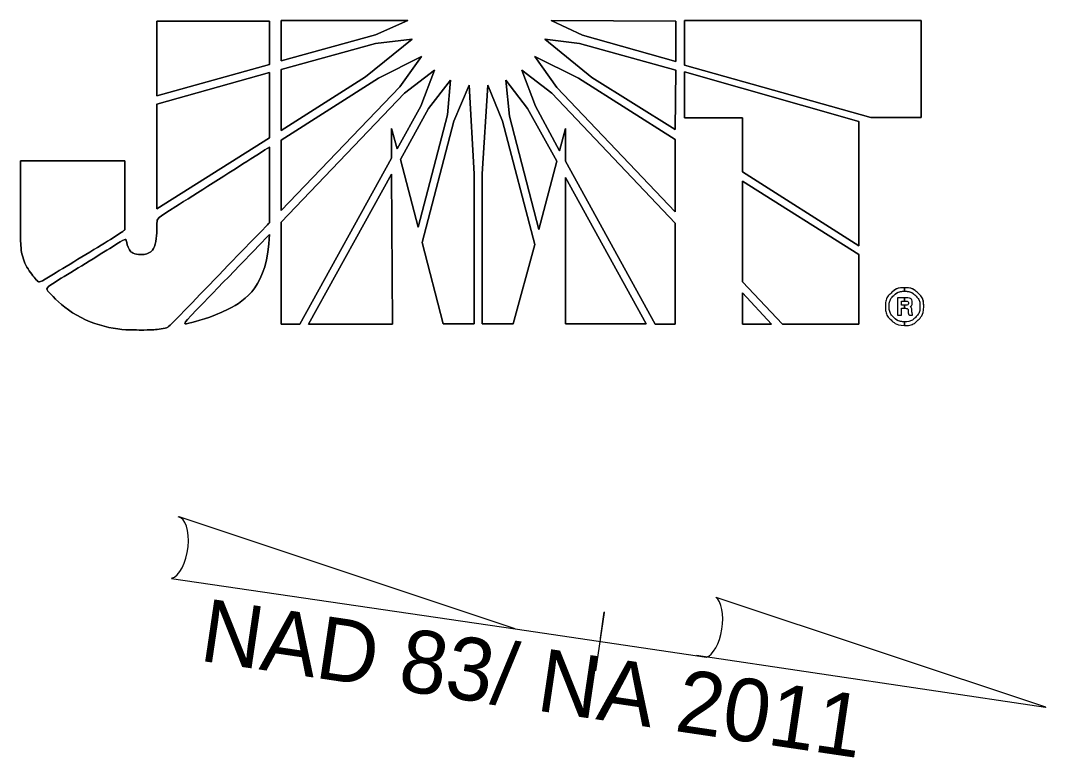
# Model space of a CAD drawing. Extents: x 0 to 4772457, y -312190 to 1506.
# Drawn here: x 3.2798 to 3.5112, y 1.3292 to 1.4956 of the extents above; entities that cross this region are included whole.
import ezdxf

# ---------------------------------------------------------------- set-up
doc = ezdxf.new("R2010")
doc.units = 0
for name, color, linetype in [('Exist Curb and Gutter', 7, 'Continuous'), ('Notes CELL', 7, 'Continuous'), ('Old_Level_63', 7, 'Continuous')]:
    doc.layers.add(name, color=color, linetype=linetype)

# ---------------------------------------------------------------- blocks, each defined once
blk = doc.blocks.new('block 2_1')
at = {"layer": 'Exist Curb and Gutter'}
for p, q in [((0.10682, 0.1325), (0.10682, 0.14026)), ((0.10682, 0.14026), (0.11852, 0.14026)), ((0.11852, 0.14026), (0.11852, 0.13575)), ((0.11973, 0.13613), (0.11973, 0.14032)), ((0.11973, 0.14032), (0.1329, 0.14032)), ((0.1329, 0.14032), (0.12954, 0.13884)), ((0.15109, 0.13878), (0.14781, 0.14032)), ((0.14781, 0.14032), (0.16078, 0.14026)), ((0.16078, 0.14026), (0.16078, 0.13606)), ((0.16169, 0.1358), (0.16169, 0.14032)), ((0.16169, 0.14032), (0.18629, 0.14032)), ((0.18629, 0.14032), (0.18629, 0.13024)), ((0.12954, 0.13884), (0.11973, 0.13613)), ((0.16078, 0.13606), (0.15109, 0.13878)), ((0.11973, 0.13523), (0.12954, 0.13793)), ((0.13337, 0.13839), (0.12852, 0.13445)), ((0.12954, 0.13793), (0.13337, 0.13839)), ((0.14715, 0.13839), (0.15076, 0.13793)), ((0.15206, 0.13438), (0.14715, 0.13839)), ((0.15076, 0.13793), (0.16078, 0.13517)), ((0.12987, 0.13432), (0.13433, 0.13658)), ((0.13433, 0.13658), (0.13207, 0.13341)), ((0.14613, 0.13658), (0.15065, 0.13432)), ((0.14839, 0.13335), (0.14613, 0.13658)), ((0.11852, 0.13575), (0.10682, 0.1325)), ((0.16169, 0.13567), (0.16169, 0.1358)), ((0.18106, 0.13024), (0.16169, 0.13567)), ((0.10682, 0.13161), (0.11852, 0.1349)), ((0.11852, 0.1349), (0.11852, 0.12812)), ((0.11973, 0.12889), (0.11973, 0.13523)), ((0.12852, 0.13445), (0.11973, 0.12889)), ((0.13257, 0.13277), (0.13568, 0.13517)), ((0.13568, 0.13517), (0.13425, 0.13142)), ((0.14476, 0.13517), (0.14787, 0.13277)), ((0.14619, 0.13142), (0.14476, 0.13517)), ((0.16071, 0.12897), (0.15206, 0.13438)), ((0.16078, 0.13517), (0.16071, 0.12897)), ((0.16169, 0.13497), (0.17982, 0.1298)), ((0.16169, 0.1349), (0.16169, 0.13497)), ((0.16169, 0.13019), (0.16169, 0.1349)), ((0.11973, 0.12787), (0.12987, 0.13432)), ((0.13207, 0.13341), (0.11973, 0.12057)), ((0.13505, 0.13115), (0.13736, 0.13412)), ((0.13736, 0.13412), (0.13704, 0.13051)), ((0.13769, 0.12986), (0.13929, 0.1336)), ((0.13929, 0.1336), (0.1398, 0.12437)), ((0.14063, 0.12437), (0.14123, 0.1336)), ((0.14123, 0.1336), (0.14277, 0.12986)), ((0.1431, 0.13412), (0.14536, 0.13115)), ((0.14348, 0.13038), (0.1431, 0.13412)), ((0.16071, 0.12043), (0.14839, 0.13335)), ((0.15065, 0.13432), (0.16071, 0.12793)), ((0.11973, 0.11933), (0.13257, 0.13277)), ((0.14787, 0.13277), (0.16071, 0.11922)), ((0.10682, 0.12071), (0.10682, 0.13161)), ((0.13425, 0.13142), (0.1318, 0.12696)), ((0.13213, 0.12586), (0.13505, 0.13115)), ((0.14536, 0.13115), (0.14839, 0.12567)), ((0.1487, 0.12677), (0.14619, 0.13142)), ((0.13704, 0.13051), (0.134, 0.11883)), ((0.14652, 0.11856), (0.14348, 0.13038)), ((0.1677, 0.13019), (0.16169, 0.13019)), ((0.1677, 0.12457), (0.1677, 0.13019)), ((0.18629, 0.13024), (0.18106, 0.13024)), ((0.1318, 0.12696), (0.13122, 0.12908)), ((0.13122, 0.12908), (0.13122, 0.126)), ((0.13439, 0.11721), (0.13769, 0.12986)), ((0.14277, 0.12986), (0.14613, 0.11702)), ((0.1493, 0.12908), (0.1487, 0.12677)), ((0.1493, 0.12567), (0.1493, 0.12908)), ((0.17982, 0.1298), (0.17982, 0.11688)), ((0.11852, 0.12812), (0.10682, 0.12071)), ((0.16071, 0.12793), (0.16071, 0.12043)), ((0.11973, 0.12057), (0.11973, 0.12787)), ((0.13122, 0.126), (0.12167, 0.10871)), ((0.134, 0.11883), (0.13213, 0.12586)), ((0.14839, 0.12567), (0.14652, 0.11856)), ((0.15864, 0.10871), (0.1493, 0.12567)), ((0.12257, 0.10871), (0.13122, 0.12432)), ((0.13122, 0.12432), (0.1313, 0.10871)), ((0.1398, 0.12437), (0.1398, 0.10877)), ((0.14063, 0.10877), (0.14063, 0.12437)), ((0.1493, 0.10877), (0.1493, 0.12399)), ((0.1493, 0.12399), (0.15768, 0.10877)), ((0.17982, 0.11688), (0.1677, 0.12457)), ((0.1677, 0.1236), (0.17982, 0.11597)), ((0.1677, 0.11314), (0.1677, 0.1236)), ((0.11973, 0.10871), (0.11973, 0.11933)), ((0.16071, 0.11922), (0.16071, 0.10871)), ((0.13659, 0.10877), (0.13439, 0.11721)), ((0.14613, 0.11702), (0.14387, 0.10877)), ((0.17982, 0.11597), (0.17982, 0.10871)), ((0.17189, 0.10871), (0.1677, 0.11314)), ((0.1677, 0.10871), (0.1677, 0.112)), ((0.1677, 0.112), (0.17073, 0.10871)), ((0.1398, 0.10877), (0.13659, 0.10877)), ((0.14387, 0.10877), (0.14063, 0.10877)), ((0.15768, 0.10877), (0.1493, 0.10877)), ((0.12167, 0.10871), (0.11973, 0.10871)), ((0.1313, 0.10871), (0.12257, 0.10871)), ((0.16071, 0.10871), (0.15864, 0.10871)), ((0.17073, 0.10871), (0.1677, 0.10871)), ((0.17982, 0.10871), (0.17189, 0.10871))]:
    blk.add_line(p, q, dxfattribs=at)
for points in [[(0.10682, 0.1325), (0.11852, 0.13575), (0.11852, 0.14026), (0.10682, 0.14026), (0.10682, 0.1325)], [(0.12954, 0.13884), (0.1329, 0.14032), (0.11973, 0.14032), (0.11973, 0.13613), (0.12954, 0.13884)], [(0.15109, 0.13878), (0.16078, 0.13606), (0.16078, 0.14026), (0.14781, 0.14032), (0.15109, 0.13878)], [(0.18629, 0.14032), (0.16169, 0.14032), (0.16169, 0.1358), (0.16169, 0.13567), (0.18106, 0.13024), (0.18629, 0.13024), (0.18629, 0.14032)], [(0.11973, 0.13523), (0.11973, 0.12889), (0.12852, 0.13445), (0.13337, 0.13839), (0.12954, 0.13793), (0.11973, 0.13523)], [(0.14715, 0.13839), (0.15206, 0.13438), (0.16071, 0.12897), (0.16078, 0.13517), (0.15076, 0.13793), (0.14715, 0.13839)], [(0.11973, 0.12787), (0.11973, 0.12057), (0.13207, 0.13341), (0.13433, 0.13658), (0.12987, 0.13432), (0.11973, 0.12787)], [(0.14613, 0.13658), (0.14839, 0.13335), (0.16071, 0.12043), (0.16071, 0.12793), (0.15065, 0.13432), (0.14613, 0.13658)], [(0.10682, 0.12071), (0.11852, 0.12812), (0.11852, 0.1349), (0.10682, 0.13161), (0.10682, 0.12071)], [(0.13568, 0.13517), (0.13257, 0.13277), (0.11973, 0.11933), (0.11973, 0.10871), (0.12167, 0.10871), (0.13122, 0.126), (0.13122, 0.12908), (0.1318, 0.12696), (0.13425, 0.13142), (0.13568, 0.13517)], [(0.14476, 0.13517), (0.14619, 0.13142), (0.1487, 0.12677), (0.1493, 0.12908), (0.1493, 0.12567), (0.15864, 0.10871), (0.16071, 0.10871), (0.16071, 0.11922), (0.14787, 0.13277), (0.14476, 0.13517)], [(0.16169, 0.13497), (0.16169, 0.1349), (0.16169, 0.13019), (0.1677, 0.13019), (0.1677, 0.12457), (0.17982, 0.11688), (0.17982, 0.1298), (0.16169, 0.13497)], [(0.13736, 0.13412), (0.13505, 0.13115), (0.13213, 0.12586), (0.134, 0.11883), (0.13704, 0.13051), (0.13736, 0.13412)], [(0.13769, 0.12986), (0.13439, 0.11721), (0.13659, 0.10877), (0.1398, 0.10877), (0.1398, 0.12437), (0.13929, 0.1336), (0.13769, 0.12986)], [(0.14123, 0.1336), (0.14063, 0.12437), (0.14063, 0.10877), (0.14387, 0.10877), (0.14613, 0.11702), (0.14277, 0.12986), (0.14123, 0.1336)], [(0.1431, 0.13412), (0.14348, 0.13038), (0.14652, 0.11856), (0.14839, 0.12567), (0.14536, 0.13115), (0.1431, 0.13412)], [(0.12257, 0.10871), (0.1313, 0.10871), (0.13122, 0.12432), (0.12257, 0.10871)], [(0.1493, 0.10877), (0.15768, 0.10877), (0.1493, 0.12399), (0.1493, 0.10877)], [(0.1677, 0.1236), (0.1677, 0.11314), (0.17189, 0.10871), (0.17982, 0.10871), (0.17982, 0.11597), (0.1677, 0.1236), (0.1677, 0.1236)], [(0.1677, 0.10871), (0.1677, 0.10871), (0.17073, 0.10871), (0.1677, 0.112), (0.1677, 0.10871)], [(0.18456, 0.11147), (0.18383, 0.11147), (0.18383, 0.10968), (0.18424, 0.10968), (0.18424, 0.11038), (0.18456, 0.11038), (0.18456, 0.1107), (0.18424, 0.1107), (0.18424, 0.11113), (0.18456, 0.11113), (0.18456, 0.11147)], [(0.18456, 0.11147), (0.18383, 0.11147), (0.18383, 0.10968), (0.18424, 0.10968), (0.18424, 0.11038), (0.18456, 0.11038)], [(0.18456, 0.1107), (0.18424, 0.1107), (0.18424, 0.11113), (0.18456, 0.11113)]]:
    blk.add_lwpolyline(points, dxfattribs=at)
for points in [[(0.10514, 0.11597), (0.10444, 0.11597), (0.10384, 0.11636), (0.10359, 0.11765), (0.10359, 0.11765), (0.09519, 0.11246), (0.09519, 0.11246), (0.09778, 0.10974), (0.10191, 0.10812), (0.10541, 0.10812), (0.10632, 0.10812), (0.10701, 0.10819), (0.10798, 0.10839), (0.10798, 0.10839), (0.11852, 0.11928), (0.11852, 0.11928), (0.11852, 0.11928), (0.11852, 0.12715), (0.11852, 0.12715), (0.11852, 0.12715), (0.10682, 0.11972), (0.10682, 0.11972), (0.10682, 0.11677), (0.1061, 0.11597), (0.10514, 0.11597)], [(0.10514, 0.11597), (0.1061, 0.11597), (0.10682, 0.11677), (0.10682, 0.11972), (0.10682, 0.11972), (0.11852, 0.12715), (0.11852, 0.12715), (0.11852, 0.12715), (0.11852, 0.11928), (0.11852, 0.11928), (0.11852, 0.11928), (0.10798, 0.10839), (0.10798, 0.10839), (0.10701, 0.10819), (0.10632, 0.10812), (0.10541, 0.10812), (0.10191, 0.10812), (0.09778, 0.10974), (0.09519, 0.11246), (0.09519, 0.11246), (0.10359, 0.11765), (0.10359, 0.11765), (0.10384, 0.11636), (0.10444, 0.11597), (0.10514, 0.11597)], [(0.10346, 0.12573), (0.10346, 0.12573), (0.09263, 0.12573), (0.09263, 0.12573), (0.09263, 0.12573), (0.09263, 0.11895), (0.09263, 0.11895), (0.09263, 0.11895), (0.09263, 0.11823), (0.09263, 0.11823), (0.09263, 0.11611), (0.09332, 0.11443), (0.09456, 0.11302), (0.09456, 0.11302), (0.10346, 0.11843), (0.10346, 0.11856), (0.10346, 0.11856), (0.10346, 0.12573), (0.10346, 0.12573)], [(0.10346, 0.12573), (0.10346, 0.12573), (0.10346, 0.11856), (0.10346, 0.11856), (0.10346, 0.11843), (0.09456, 0.11302), (0.09456, 0.11302), (0.09332, 0.11443), (0.09263, 0.11611), (0.09263, 0.11823), (0.09263, 0.11823), (0.09263, 0.11895), (0.09263, 0.11895), (0.09263, 0.11895), (0.09263, 0.12573), (0.09263, 0.12573), (0.09263, 0.12573), (0.10346, 0.12573), (0.10346, 0.12573)], [(0.11852, 0.11804), (0.11852, 0.11804), (0.1094, 0.10864), (0.1094, 0.10864), (0.11386, 0.10974), (0.11831, 0.11269), (0.11852, 0.11804)], [(0.11852, 0.11804), (0.11831, 0.11269), (0.11386, 0.10974), (0.1094, 0.10864), (0.1094, 0.10864), (0.11852, 0.11804), (0.11852, 0.11804)], [(0.18456, 0.10859), (0.18403, 0.10859), (0.18355, 0.10878), (0.18316, 0.10917), (0.18277, 0.10955), (0.18258, 0.11002), (0.18258, 0.11057), (0.18258, 0.11113), (0.18277, 0.1116), (0.18316, 0.11195), (0.18355, 0.11233), (0.18401, 0.11252), (0.18456, 0.11252), (0.18456, 0.11252), (0.18456, 0.11215), (0.18456, 0.11215), (0.18412, 0.11215), (0.18375, 0.112), (0.18344, 0.11171), (0.18313, 0.1114), (0.18297, 0.11101), (0.18297, 0.11057), (0.18297, 0.11013), (0.18313, 0.10974), (0.18344, 0.10943), (0.18375, 0.10913), (0.18412, 0.10898), (0.18456, 0.10898), (0.18456, 0.10898), (0.18456, 0.10859), (0.18456, 0.10859), (0.18456, 0.10859), (0.18456, 0.10859), (0.18456, 0.10859)], [(0.18456, 0.11252), (0.18401, 0.11252), (0.18355, 0.11233), (0.18316, 0.11195), (0.18277, 0.1116), (0.18258, 0.11113), (0.18258, 0.11057), (0.18258, 0.11002), (0.18277, 0.10955), (0.18316, 0.10917), (0.18355, 0.10878), (0.18403, 0.10859), (0.18456, 0.10859)], [(0.18456, 0.10898), (0.18412, 0.10898), (0.18375, 0.10913), (0.18344, 0.10943), (0.18313, 0.10974), (0.18297, 0.11013), (0.18297, 0.11057), (0.18297, 0.11101), (0.18313, 0.1114), (0.18344, 0.11171), (0.18375, 0.112), (0.18412, 0.11215), (0.18456, 0.11215)], [(0.18656, 0.11057), (0.18656, 0.11002), (0.18637, 0.10955), (0.18599, 0.10916), (0.1856, 0.10878), (0.18513, 0.10859), (0.18458, 0.10859), (0.18458, 0.10859), (0.18458, 0.10859), (0.18456, 0.10859), (0.18456, 0.10859), (0.18456, 0.10898), (0.18456, 0.10898), (0.18458, 0.10898), (0.18458, 0.10898), (0.18458, 0.10898), (0.18502, 0.10898), (0.18539, 0.10913), (0.1857, 0.10943), (0.18601, 0.10974), (0.18617, 0.11013), (0.18617, 0.11057), (0.18617, 0.11101), (0.18601, 0.1114), (0.1857, 0.11171), (0.18539, 0.112), (0.18502, 0.11215), (0.18456, 0.11215), (0.18456, 0.11215), (0.18456, 0.11252), (0.18456, 0.11252), (0.18512, 0.11252), (0.18559, 0.11233), (0.18598, 0.11195), (0.18637, 0.1116), (0.18656, 0.11113), (0.18656, 0.11057), (0.18656, 0.11057), (0.18656, 0.11057), (0.18656, 0.11057)], [(0.18656, 0.11057), (0.18656, 0.11113), (0.18637, 0.1116), (0.18598, 0.11195), (0.18559, 0.11233), (0.18512, 0.11252), (0.18456, 0.11252)], [(0.18456, 0.11215), (0.18502, 0.11215), (0.18539, 0.112), (0.1857, 0.11171), (0.18601, 0.1114), (0.18617, 0.11101), (0.18617, 0.11057), (0.18617, 0.11013), (0.18601, 0.10974), (0.1857, 0.10943), (0.18539, 0.10913), (0.18502, 0.10898), (0.18458, 0.10898), (0.18458, 0.10898), (0.18458, 0.10898), (0.18456, 0.10898)], [(0.18456, 0.11038), (0.18456, 0.11038), (0.18456, 0.1107), (0.18456, 0.1107), (0.18456, 0.1107), (0.18458, 0.1107), (0.18458, 0.1107), (0.18484, 0.1107), (0.18497, 0.11078), (0.18497, 0.11093), (0.18497, 0.11106), (0.18485, 0.11113), (0.18461, 0.11113), (0.18461, 0.11113), (0.18456, 0.11113), (0.18456, 0.11113), (0.18456, 0.11113), (0.18456, 0.11147), (0.18456, 0.11147), (0.18456, 0.11147), (0.18468, 0.11147), (0.18468, 0.11147), (0.18513, 0.11147), (0.18536, 0.11129), (0.18536, 0.11093), (0.18536, 0.11077), (0.18529, 0.11064), (0.18515, 0.11054), (0.18526, 0.11048), (0.18533, 0.11033), (0.18534, 0.1101), (0.18534, 0.1101), (0.18534, 0.11), (0.18534, 0.11), (0.18534, 0.11), (0.18536, 0.10994), (0.18536, 0.10994), (0.18536, 0.10994), (0.18536, 0.10987), (0.18536, 0.10987), (0.18536, 0.10987), (0.18541, 0.10968), (0.18541, 0.10968), (0.18541, 0.10968), (0.18503, 0.10968), (0.18503, 0.10968), (0.18499, 0.10978), (0.18495, 0.10987), (0.18495, 0.11), (0.18495, 0.11017), (0.18494, 0.11026), (0.18489, 0.11031), (0.18484, 0.11034), (0.18474, 0.11038), (0.18458, 0.11038), (0.18458, 0.11038), (0.18456, 0.11038), (0.18456, 0.11038)], [(0.18456, 0.11038), (0.18456, 0.11038), (0.18458, 0.11038), (0.18458, 0.11038), (0.18474, 0.11038), (0.18484, 0.11034), (0.18489, 0.11031), (0.18494, 0.11026), (0.18495, 0.11017), (0.18495, 0.11), (0.18495, 0.10987), (0.18499, 0.10978), (0.18503, 0.10968), (0.18503, 0.10968), (0.18541, 0.10968), (0.18541, 0.10968), (0.18541, 0.10968), (0.18536, 0.10987), (0.18536, 0.10987), (0.18536, 0.10987), (0.18536, 0.10994), (0.18536, 0.10994), (0.18536, 0.10994), (0.18534, 0.11), (0.18534, 0.11), (0.18534, 0.11), (0.18534, 0.1101), (0.18534, 0.1101), (0.18533, 0.11033), (0.18526, 0.11048), (0.18515, 0.11054), (0.18529, 0.11064), (0.18536, 0.11077), (0.18536, 0.11093), (0.18536, 0.11129), (0.18513, 0.11147), (0.18468, 0.11147), (0.18468, 0.11147), (0.18456, 0.11147), (0.18456, 0.11147)], [(0.18456, 0.11113), (0.18456, 0.11113), (0.18461, 0.11113), (0.18461, 0.11113), (0.18485, 0.11113), (0.18497, 0.11106), (0.18497, 0.11093), (0.18497, 0.11078), (0.18484, 0.1107), (0.18458, 0.1107), (0.18458, 0.1107), (0.18456, 0.1107), (0.18456, 0.1107)], [(0.18456, 0.10859), (0.18458, 0.10859), (0.18458, 0.10859), (0.18458, 0.10859), (0.18513, 0.10859), (0.1856, 0.10878), (0.18599, 0.10916), (0.18637, 0.10955), (0.18656, 0.11002), (0.18656, 0.11057)]]:
    blk.add_open_spline(points, degree=3, dxfattribs=at)

msp = doc.modelspace()

# ---------------------------------------------------------------- linework, layer by layer
at = {"layer": 'Notes CELL'}
for p, q in [((3.39153, 1.35821), (3.31567, 1.3835)), ((3.31395, 1.3696), (3.39153, 1.35821)), ((3.43682, 1.3654), (3.51124, 1.34057)), ((3.41162, 1.36189), (3.40967, 1.3487)), ((3.41077, 1.35612), (3.41163, 1.36197)), ((3.41163, 1.36197), (3.41165, 1.36205)), ((3.39153, 1.35821), (3.43473, 1.35181)), ((3.51123, 1.34049), (3.43242, 1.35216)), ((3.43242, 1.35216), (3.43465, 1.35183)), ((3.51123, 1.34049), (3.51122, 1.34041)), ((3.51123, 1.34049), (3.51122, 1.34041))]:
    msp.add_line(p, q, dxfattribs=at)
for centre, start_param, end_param in [((3.31436, 1.37656), 0.201328, 3.141593), ((3.435, 1.3587), 0.216388, 2.908219)]:
    msp.add_ellipse(centre, major_axis=(-0.00108, -0.00697), ratio=0.461098, start_param=start_param, end_param=end_param, dxfattribs=at)

# ---------------------------------------------------------------- block references
at = {"layer": 'Old_Level_63', "xscale": 2.170686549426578, "yscale": 2.170686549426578}
msp.add_blockref('block 2_1', (3.07878, 1.19101), dxfattribs=at)

# ---------------------------------------------------------------- texts
at = {"layer": 'Notes CELL'}
msp.add_text('NAD 83/ NA 2011', height=0.0141667, rotation=351.5819, dxfattribs=at).set_placement((3.31999, 1.35107))

doc.saveas('drawing.dxf')
